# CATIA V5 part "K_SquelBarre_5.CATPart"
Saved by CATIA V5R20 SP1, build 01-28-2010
Part number: squelette_barre_5
Publications: "Point.1", "Point.2", "Plan.1", "Droite.1", "Droite.2", "Droite.3"
Bounding box of the stored display mesh (mm): x 0 to 0, y 0 to 20, z 0 to 35
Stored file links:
  G:\Khaled_CFAO_2011\ST2M\ST2M_GR2\gcausse\Khaled\CAD_ThinkMotion\K_SquelBarre_5.CATPart
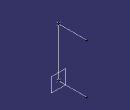
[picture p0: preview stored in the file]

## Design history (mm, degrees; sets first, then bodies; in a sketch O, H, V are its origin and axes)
Set1
  Point1: (0, 0, 0)
  Point2: (0, 0, 35)
  Plane1: type Offset, RefPlane zx-plane, Offset 0
  Line1: type PtPt, FirstPoint Point2, SecondPoint Point1
  Line2: type PtDir, RefPoint Point2, Direction Plane1, Start 0, End 20
  Line3: type PtDir, RefPoint Point1, Direction Plane1, Start 0, End 20
Body1 (main body)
